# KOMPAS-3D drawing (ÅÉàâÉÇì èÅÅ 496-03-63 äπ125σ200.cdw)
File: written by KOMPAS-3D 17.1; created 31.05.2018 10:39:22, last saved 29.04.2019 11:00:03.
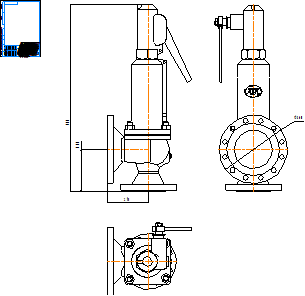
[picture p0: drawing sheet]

Sheet 1: A4, portrait

Title block, sheet 1: name: Прегран Ду125х200; material: Внимание! Данный продукт является объектом авторского права ООО «Торговый Дом АДЛ». / Запрещается изменение, копирование, распространение / (в том числе путем копирования на другие сайты и ресурсы в Интернете) / или любое иное использование информации и объектов без предварительного / согласия правообладателя (ООО «Торговый Дом АДЛ»).; sheets: 1; organisation: ООО "Торговый дом АДЛ"; sheet format: A4; stored path: C:\Users\tra\Desktop\2д чертежи\Предохранительные клапаны ПРЕГРАН\ПРЕГРАН 496\ПРЕГРАН КПП 496-03-63\KOMPAS 2D\Прегран Ду125х200.cdw

Views: Вид 1, Проекционный вид 2, Проекционный вид 4
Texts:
  kka
  adl
Dimensions and other numbers on the sheet: 980; 220; 215; 360; 1:1; 1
